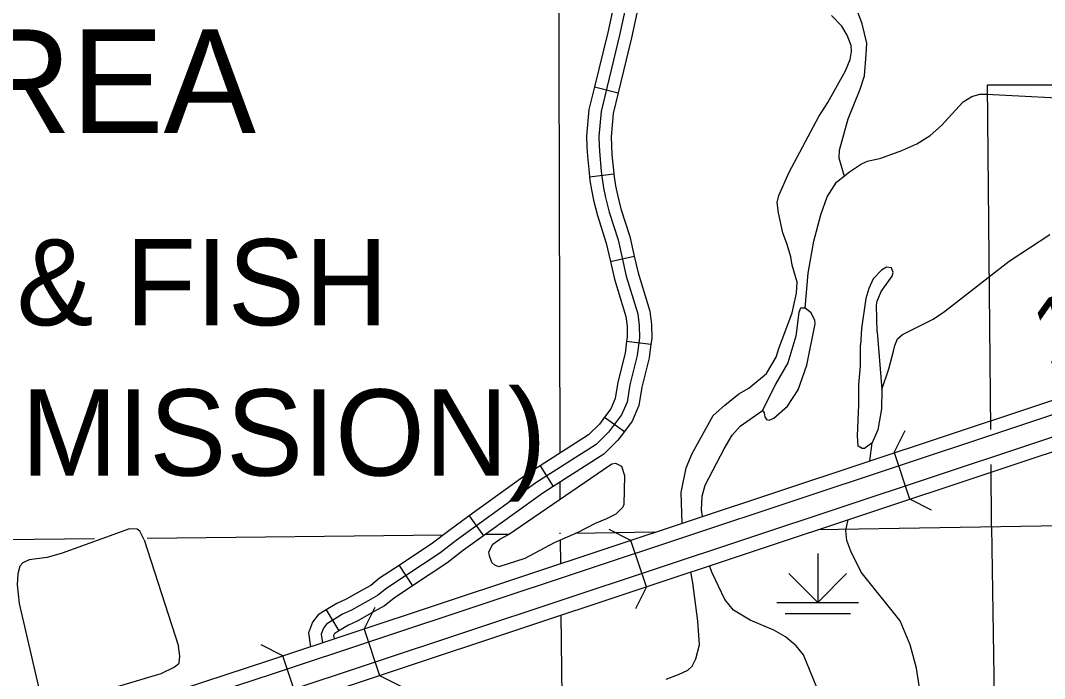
# Model space of a CAD drawing. Extents: x 1084508 to 1142749, y 1057638 to 1093403.
# Drawn here: x 1091747 to 1093716, y 1071794 to 1073059 of the extents above; entities that cross this region are included whole.
import ezdxf

# ---------------------------------------------------------------- set-up
doc = ezdxf.new("R2010")
doc.units = 0
for name, color, linetype in [('Level 19', 7, 'Continuous'), ('Level 32', 7, 'Continuous'), ('Level 35', 7, 'Continuous'), ('Level 39', 7, 'Continuous'), ('Level 44', 7, 'Continuous'), ('Level 47', 7, 'Continuous'), ('Level 48', 7, 'Continuous'), ('Level 5', 7, 'Continuous'), ('Level 7', 7, 'Continuous')]:
    doc.layers.add(name, color=color, linetype=linetype)

msp = doc.modelspace()

# ---------------------------------------------------------------- linework, layer by layer
at = {"layer": 'Level 19'}
for points in [[(1086828.8, 1069564.8), (1086958.3, 1069597.9), (1087305.2, 1069683.8), (1087445.9, 1069710.7), (1087821, 1069773.1), (1088253.5, 1069840.9), (1088436.6, 1069876.1), (1088626, 1069927.2), (1088752.5, 1069969), (1088851.8, 1070006.5), (1088959.6, 1070052.9), (1089051.3, 1070099.1), (1089145.7, 1070149.3), (1089264, 1070224), (1089345.2, 1070271.9), (1090501.3, 1071000.2), (1091111.9, 1071388.7), (1091276, 1071487.3), (1091344.3, 1071524.2), (1091404.7, 1071552.9), (1091443.8, 1071569.2), (1091605.2, 1071625.7), (1092224.5, 1071828.5), (1094022, 1072425.4)], [(1094030.9, 1072400.2), (1092232.9, 1071803.1), (1091613.8, 1071600.4), (1091453.4, 1071544.3), (1091415.6, 1071528.5), (1091356.3, 1071500.4), (1091289.2, 1071464.1), (1091126, 1071366), (1090515.6, 1070977.7), (1089359.1, 1070249.2), (1089277.9, 1070201.2), (1089159.1, 1070126.2), (1089063.6, 1070075.4), (1088970.9, 1070028.7), (1088861.8, 1069981.8), (1088761.4, 1069943.9), (1088633.7, 1069901.6), (1088442.6, 1069850.1), (1088258.1, 1069814.7), (1087825.3, 1069746.7), (1087450.6, 1069684.4), (1087310.9, 1069657.7), (1086964.9, 1069572), (1086833.1, 1069538.3)], [(1094044.5, 1072361.7), (1092245.7, 1071764.4), (1091626.8, 1071561.8), (1091468, 1071506.2), (1091432.2, 1071491.3), (1091374.8, 1071464), (1091309.5, 1071428.7), (1091147.4, 1071331.3), (1090537.4, 1070943.2), (1089380.4, 1070214.3), (1089299.2, 1070166.4), (1089179.6, 1070090.9), (1089082.3, 1070039.1), (1088988.1, 1069991.7), (1088877.1, 1069943.9), (1088775, 1069905.4), (1088645.4, 1069862.5), (1088451.8, 1069810.3), (1088265.1, 1069774.4), (1087831.8, 1069706.5), (1087457.7, 1069644.3), (1087319.6, 1069617.8), (1086974.8, 1069532.5), (1086844.1, 1069499)], [(1086853, 1069473.8), (1086981.3, 1069506.6), (1087325.3, 1069591.8), (1087462.4, 1069618), (1087836, 1069680.1), (1088269.7, 1069748.2), (1088457.8, 1069784.3), (1088653.1, 1069837), (1088783.9, 1069880.3), (1088887.1, 1069919.2), (1088999.4, 1069967.5), (1089094.6, 1070015.5), (1089193, 1070067.8), (1089313.1, 1070143.6), (1089394.3, 1070191.5), (1090551.7, 1070920.7), (1091161.5, 1071308.6), (1091322.7, 1071405.5), (1091386.9, 1071440.2), (1091443.1, 1071466.9), (1091477.6, 1071481.3), (1091635.4, 1071536.5), (1092254, 1071739), (1094053.4, 1072336.6)]]:
    msp.add_lwpolyline(points, dxfattribs=at)
at = {"layer": 'Level 32'}
for p, q in [((1092850.9, 1072931.1), (1092896.6, 1072920)), ((1092841.5, 1072758.4), (1092888.2, 1072764.4)), ((1092881.6, 1072595.6), (1092927.6, 1072606)), ((1092912.9, 1072442.4), (1092959.6, 1072436.5)), ((1092870.6, 1072296.6), (1092908.5, 1072268.8)), ((1092746.3, 1072203.1), (1092771.5, 1072163.3)), ((1092609.9, 1072106.5), (1092637.5, 1072068.3)), ((1092475.4, 1072011.5), (1092501.3, 1071972.2)), ((1092335, 1071925.8), (1092359.6, 1071885.6))]:
    msp.add_line(p, q, dxfattribs=at)
for points in [[(1092531.1, 1073694.1), (1092610.1, 1073671.9), (1092649.7, 1073656.2), (1092682.3, 1073638.1), (1092764.5, 1073605.2), (1092814, 1073571.4), (1092841.3, 1073543.8), (1092856.1, 1073519.6), (1092875.2, 1073493.6), (1092912.8, 1073429.6), (1092918.7, 1073414.7), (1092921.7, 1073387.7), (1092918, 1073328.3), (1092919.5, 1073193.8), (1092914.1, 1073098.3), (1092899.3, 1073030.6), (1092863.7, 1072884.1), (1092859.4, 1072835.7), (1092860.1, 1072817.2), (1092861.2, 1072799.7), (1092864, 1072768.4)], [(1092888.6, 1073091.9), (1092876.4, 1073035.9), (1092850.9, 1072931.1)], [(1092934.6, 1073081.9), (1092922.3, 1073025.3), (1092896.6, 1072920)], [(1092850.9, 1072931.1), (1092840.4, 1072887.9), (1092835.8, 1072836.3), (1092836.6, 1072816.1), (1092837.7, 1072797.9), (1092840.6, 1072765.9), (1092841.5, 1072758.4)], [(1092896.6, 1072920), (1092887, 1072880.2), (1092883, 1072835.1), (1092883.6, 1072818.4), (1092884.6, 1072801.4), (1092887.4, 1072771), (1092888.2, 1072764.4)], [(1092864, 1072768.4), (1092865.7, 1072754.7), (1092868.5, 1072737.1), (1092872, 1072718.9), (1092879.2, 1072690.4), (1092896.3, 1072637.3), (1092912.2, 1072567.4), (1092934.1, 1072495), (1092937.1, 1072472.8), (1092937.4, 1072448.9), (1092933.1, 1072414.8), (1092919.3, 1072358.6), (1092913.7, 1072325.4), (1092902.7, 1072300.7), (1092878.3, 1072267.4), (1092854.5, 1072243.8), (1092738.2, 1072170), (1092584.8, 1072059.3), (1092553.5, 1072034.8), (1092451.7, 1071967.7), (1092434, 1071953.4), (1092415.6, 1071943.1)], [(1092888.2, 1072764.4), (1092889, 1072758.1), (1092891.7, 1072741.2), (1092895, 1072724), (1092901.9, 1072696.9), (1092919, 1072643.5), (1092927.6, 1072606)], [(1092841.5, 1072758.4), (1092842.4, 1072751.4), (1092845.3, 1072733.1), (1092849.1, 1072713.8), (1092856.6, 1072683.9), (1092873.6, 1072631), (1092881.6, 1072595.6)], [(1092927.6, 1072606), (1092934.9, 1072573.5), (1092957.2, 1072500.1), (1092960.7, 1072474.6), (1092961, 1072447.6), (1092959.6, 1072436.5)], [(1092881.6, 1072595.6), (1092889.4, 1072561.4), (1092911, 1072490), (1092913.6, 1072471.1), (1092913.9, 1072450.3), (1092912.9, 1072442.4)], [(1092912.9, 1072442.4), (1092909.9, 1072419.1), (1092896.2, 1072363.4), (1092891, 1072332.2), (1092882.2, 1072312.6), (1092870.6, 1072296.6)], [(1092959.6, 1072436.5), (1092956.3, 1072410.5), (1092942.4, 1072353.8), (1092936.4, 1072318.5), (1092923.2, 1072288.9), (1092908.5, 1072268.8)], [(1092870.6, 1072296.6), (1092860.4, 1072282.8), (1092839.7, 1072262.3), (1092746.3, 1072203.1)], [(1092908.5, 1072268.8), (1092896.2, 1072252), (1092869.2, 1072225.3), (1092771.5, 1072163.3)], [(1092746.3, 1072203.1), (1092725, 1072189.5), (1092609.9, 1072106.5)], [(1092771.5, 1072163.3), (1092751.4, 1072150.5), (1092637.5, 1072068.3)], [(1092609.9, 1072106.5), (1092570.7, 1072078.1), (1092539.7, 1072053.9), (1092475.4, 1072011.5)], [(1092637.5, 1072068.3), (1092598.9, 1072040.5), (1092567.2, 1072015.7), (1092501.3, 1071972.2)], [(1092475.4, 1072011.5), (1092437.8, 1071986.7), (1092420.8, 1071973), (1092404.1, 1071963.7), (1092373.2, 1071946.4), (1092355.6, 1071938.4), (1092335, 1071925.8)], [(1092501.3, 1071972.2), (1092465.6, 1071948.7), (1092447.2, 1071933.8), (1092427.1, 1071922.6), (1092394.5, 1071904.3), (1092377.7, 1071896.7), (1092359.6, 1071885.6)], [(1092415.6, 1071943.1), (1092383.9, 1071925.4), (1092366.7, 1071917.5), (1092335.6, 1071898.5), (1092329.8, 1071890.9), (1092325.2, 1071879.1), (1092327.8, 1071862.5)], [(1092335, 1071925.8), (1092319.5, 1071916.3), (1092309, 1071902.5), (1092301, 1071881.7), (1092305.1, 1071855.2)], [(1092359.6, 1071885.6), (1092351.6, 1071880.7), (1092350.5, 1071879.3), (1092349.4, 1071876.5), (1092350.4, 1071870.3)]]:
    msp.add_lwpolyline(points, dxfattribs=at)
at = {"layer": 'Level 35'}
for points in [[(1093331.3, 1072760.6), (1093321.5, 1072793.9), (1093322.4, 1072809.7), (1093339.1, 1072870), (1093362.1, 1072927.1), (1093370.5, 1072952.6), (1093373.8, 1072993.4), (1093374.5, 1073015.2), (1093366, 1073052.7), (1093355.4, 1073080.3), (1093339.7, 1073109.3), (1093302.9, 1073162.9), (1093289.3, 1073186.9), (1093278.8, 1073210.7), (1093267.9, 1073253.8), (1093267.4, 1073289.1), (1093278.6, 1073372.4)], [(1093341.4, 1072768.2), (1093364.4, 1072783.1), (1093375.8, 1072788.6), (1093401.4, 1072794.1), (1093442.3, 1072808.8), (1093470.7, 1072821.6), (1093496.4, 1072838.1), (1093518.6, 1072856.7), (1093531.2, 1072871.4), (1093560.1, 1072902.3), (1093576.6, 1072913), (1093591.8, 1072917.2), (1093604.7, 1072917.1), (1093803, 1072907.1)], [(1093255.9, 1072506), (1093262.2, 1072573.1), (1093272.7, 1072634.5), (1093286.1, 1072685.5), (1093298.8, 1072719.6), (1093316.4, 1072747.8), (1093341.4, 1072768.2)], [(1093394.7, 1072460.7), (1093393.4, 1072511.6), (1093394.4, 1072519.1), (1093402.5, 1072538), (1093423.2, 1072567.6), (1093425.5, 1072574.5), (1093422.4, 1072583.6), (1093412.6, 1072584.5), (1093402.8, 1072579.1), (1093387, 1072562.3), (1093378.8, 1072543.8), (1093372.6, 1072524.7), (1093364.4, 1072466.6), (1093362.9, 1072435.4)], [(1093255.9, 1072506), (1093247.4, 1072505.7), (1093243.9, 1072497.4), (1093238.1, 1072452.2), (1093222.9, 1072400.8), (1093199.4, 1072359.5), (1093174.4, 1072309), (1093177.1, 1072304.7), (1093178.3, 1072296.8), (1093181.9, 1072291.9), (1093187.2, 1072290.8), (1093195.9, 1072294.6), (1093222.4, 1072317.8), (1093242.4, 1072348.9), (1093259.7, 1072396.3), (1093275.6, 1072475.5), (1093274.8, 1072482.4), (1093267.4, 1072496.6), (1093255.9, 1072506)], [(1093394.7, 1072460.7), (1093403.3, 1072349.3), (1093403.2, 1072312.2), (1093396, 1072272), (1093385.2, 1072247.2), (1093370.2, 1072236), (1093365.8, 1072236.2), (1093358.2, 1072240.6), (1093356.9, 1072260.7), (1093359.1, 1072320.2), (1093359.4, 1072359.2), (1093362.7, 1072394.2), (1093362.9, 1072435.4)], [(1093058.5, 1072105.4), (1093057.1, 1072118), (1093058.4, 1072144.5), (1093064, 1072165.8), (1093100.6, 1072235.8), (1093115.8, 1072261.5), (1093131.5, 1072279), (1093174.4, 1072309)], [(1092868.4, 1072195.9), (1092884.3, 1072206.5), (1092891.2, 1072207.9), (1092902.9, 1072202.4), (1092908.9, 1072184.3), (1092907.2, 1072128.6), (1092905.8, 1072123.2), (1092892.4, 1072110.2), (1092874.2, 1072100.8), (1092852.3, 1072091.9), (1092819.3, 1072074.8), (1092773.2, 1072055), (1092717.2, 1072024.6), (1092666.9, 1072008.5), (1092659.6, 1072012), (1092653.8, 1072016.9), (1092649.3, 1072029.9), (1092648.1, 1072037.7), (1092655.8, 1072052.1), (1092669.3, 1072062), (1092685.6, 1072070.7)], [(1092685.6, 1072070.7), (1092868.4, 1072195.9)], [(1091985.3, 1072060.6), (1091977, 1072077), (1091971.5, 1072080.9), (1091957.1, 1072081.7), (1091827.3, 1072034.7), (1091798.4, 1072026.5), (1091763.8, 1072021.9), (1091751.4, 1072016.5), (1091746, 1072010), (1091742.1, 1071995.4), (1091740.5, 1071974), (1091744.8, 1071938.3), (1091783.1, 1071772.3), (1091786.5, 1071751.6), (1091794.1, 1071741.8), (1091802.3, 1071739.6), (1092018, 1071803.5), (1092043, 1071816), (1092052.2, 1071823.8), (1092053.6, 1071837.1), (1092050.8, 1071855.9)], [(1091985.3, 1072060.6), (1092050.8, 1071855.9)], [(1093619.5, 1070930.3), (1093565.3, 1071007.8), (1093552.4, 1071029.1), (1093526.7, 1071087.7), (1093497.4, 1071160.9), (1093473.5, 1071240.9), (1093440.7, 1071344.6), (1093424.4, 1071405.6), (1093407.5, 1071451.3), (1093356.6, 1071563.8), (1093325, 1071641.4), (1093290.2, 1071748.4), (1093252.8, 1071839.3), (1093239.1, 1071856.7), (1093218.5, 1071874.3), (1093196.1, 1071887.1), (1093150.4, 1071906.4), (1093118.4, 1071925.1), (1093101.5, 1071945.6), (1093077.3, 1071997), (1093072.3, 1072010.8)]]:
    msp.add_lwpolyline(points, dxfattribs=at)
at = {"layer": 'Level 39'}
for p, q in [((1093427.1, 1072228.6), (1093448.2, 1072270.7)), ((1093427.1, 1072228.6), (1093456.7, 1072139.3)), ((1093456.7, 1072139.3), (1093498.8, 1072118.2)), ((1092921.2, 1072059.5), (1092879.1, 1072080.6)), ((1092950.9, 1071970.2), (1092921.2, 1072059.5)), ((1092950.9, 1071970.2), (1092929.8, 1071928.1)), ((1092408.1, 1071888.9), (1092429.2, 1071931)), ((1092408.1, 1071888.9), (1092437.7, 1071799.6)), ((1092251.9, 1071837.5), (1092209.8, 1071858.6)), ((1092281.5, 1071748.1), (1092251.9, 1071837.5)), ((1092437.7, 1071799.6), (1092479.8, 1071778.5))]:
    msp.add_line(p, q, dxfattribs=at)
at = {"layer": 'Level 44'}
for p, q in [((1093280.3, 1072034.3), (1093280.3, 1071940.1)), ((1093280.3, 1071940.1), (1093224.9, 1071995.6)), ((1093280.3, 1071940.1), (1093335.8, 1071995.6)), ((1093201.9, 1071940.1), (1093358.8, 1071940.1)), ((1093217.6, 1071918.8), (1093343.1, 1071918.8))]:
    msp.add_line(p, q, dxfattribs=at)
at = {"layer": 'Level 47'}
for points in [[(1093225.5, 1072767.2), (1093282.6, 1072874.6), (1093300, 1072901.1), (1093333.6, 1072962.4), (1093342.5, 1072983.9), (1093345.3, 1072999.5), (1093344.5, 1073010.8), (1093337, 1073030.4), (1093326.6, 1073047.9), (1093306.8, 1073068.2)], [(1093019.7, 1072092.5), (1093017.8, 1072151.7), (1093027.5, 1072199.1), (1093038.9, 1072226.2), (1093079.5, 1072299.3), (1093101.7, 1072319.5), (1093128.9, 1072341.4), (1093147.7, 1072352.4), (1093181.8, 1072380.6), (1093200.3, 1072411.4), (1093205.4, 1072428.5), (1093231.1, 1072496.7), (1093239.6, 1072534.4), (1093240.5, 1072555.8), (1093231, 1072588.5), (1093228.6, 1072604.4), (1093221.8, 1072628.4), (1093213, 1072650.8), (1093205.2, 1072688.9), (1093202.6, 1072709.2), (1093205.7, 1072722.2), (1093225.5, 1072767.2)], [(1093426.2, 1072423.4), (1093428.3, 1072434.3), (1093433.9, 1072446.7), (1093443.3, 1072455.5), (1093502.2, 1072484.8), (1093524, 1072499.7), (1093648.7, 1072596.2), (1093726.4, 1072647.5)], [(1093403.3, 1072349.3), (1093417, 1072389.4), (1093426.2, 1072423.4)], [(1093380.5, 1072212.3), (1093385.2, 1072247.2)], [(1093478.1, 1071763.3), (1093470.2, 1071813.7), (1093458.1, 1071858.6), (1093439, 1071905.1), (1093364, 1071998.2), (1093344.2, 1072038.5), (1093336.3, 1072059.6), (1093334.4, 1072078.7), (1093339.1, 1072099.4)], [(1093052.9, 1071858.5), (1093049.6, 1071904), (1093040.3, 1071977.9), (1093036.4, 1071998.8)], [(1092988.8, 1071792.7), (1093012.9, 1071801.5), (1093030.4, 1071810.1), (1093038.6, 1071818), (1093045.8, 1071831.8), (1093052.9, 1071858.5)]]:
    msp.add_lwpolyline(points, dxfattribs=at)
at = {"layer": 'Level 5'}
for points in [[(1092780.9, 1073492.9), (1092784.3, 1072227.2)], [(1092784.4, 1072171.5), (1092784.5, 1072138.4)], [(1094624.7, 1072101.5), (1094451, 1072098.9), (1093280.9, 1072080)], [(1092784.7, 1072073.9), (1092784.7, 1072072)], [(1092966.8, 1072075), (1092813.9, 1072072.5)], [(1091889.3, 1072062.3), (1091135.1, 1072054.1), (1090506.9, 1072055.8)], [(1092559.7, 1072069.6), (1091990.7, 1072063.4)], [(1092686, 1072071), (1092640.5, 1072070.5)], [(1092784.8, 1072060), (1092785.4, 1072014.7)], [(1092786.6, 1071915.9), (1092789.1, 1071706.6)]]:
    msp.add_lwpolyline(points, dxfattribs=at)
at = {"layer": 'Level 7'}
for points in [[(1093613, 1072272.6), (1093606.8, 1072935.1), (1094437.4, 1072935.1)], [(1093614.8, 1072085.4), (1093613.7, 1072205.1)], [(1093614.8, 1072085.4), (1093641, 1070404.5)]]:
    msp.add_lwpolyline(points, dxfattribs=at)

# ---------------------------------------------------------------- texts
at = {"layer": 'Level 48'}
msp.add_text('10.4', height=132.58, rotation=17.5064, dxfattribs=at).set_placement((1093720.4, 1072385.9))
at = {"layer": 'Level 7'}
for s, height, p in [('AREA', 198.88, (1091475.7, 1072842.8)), ('(ARK GAME & FISH', 165.73, (1090434.4, 1072473)), ('COMMISSION)', 165.73, (1091231.8, 1072184))]:
    msp.add_text(s, height=height, dxfattribs=at).set_placement(p)

doc.saveas('drawing.dxf')
